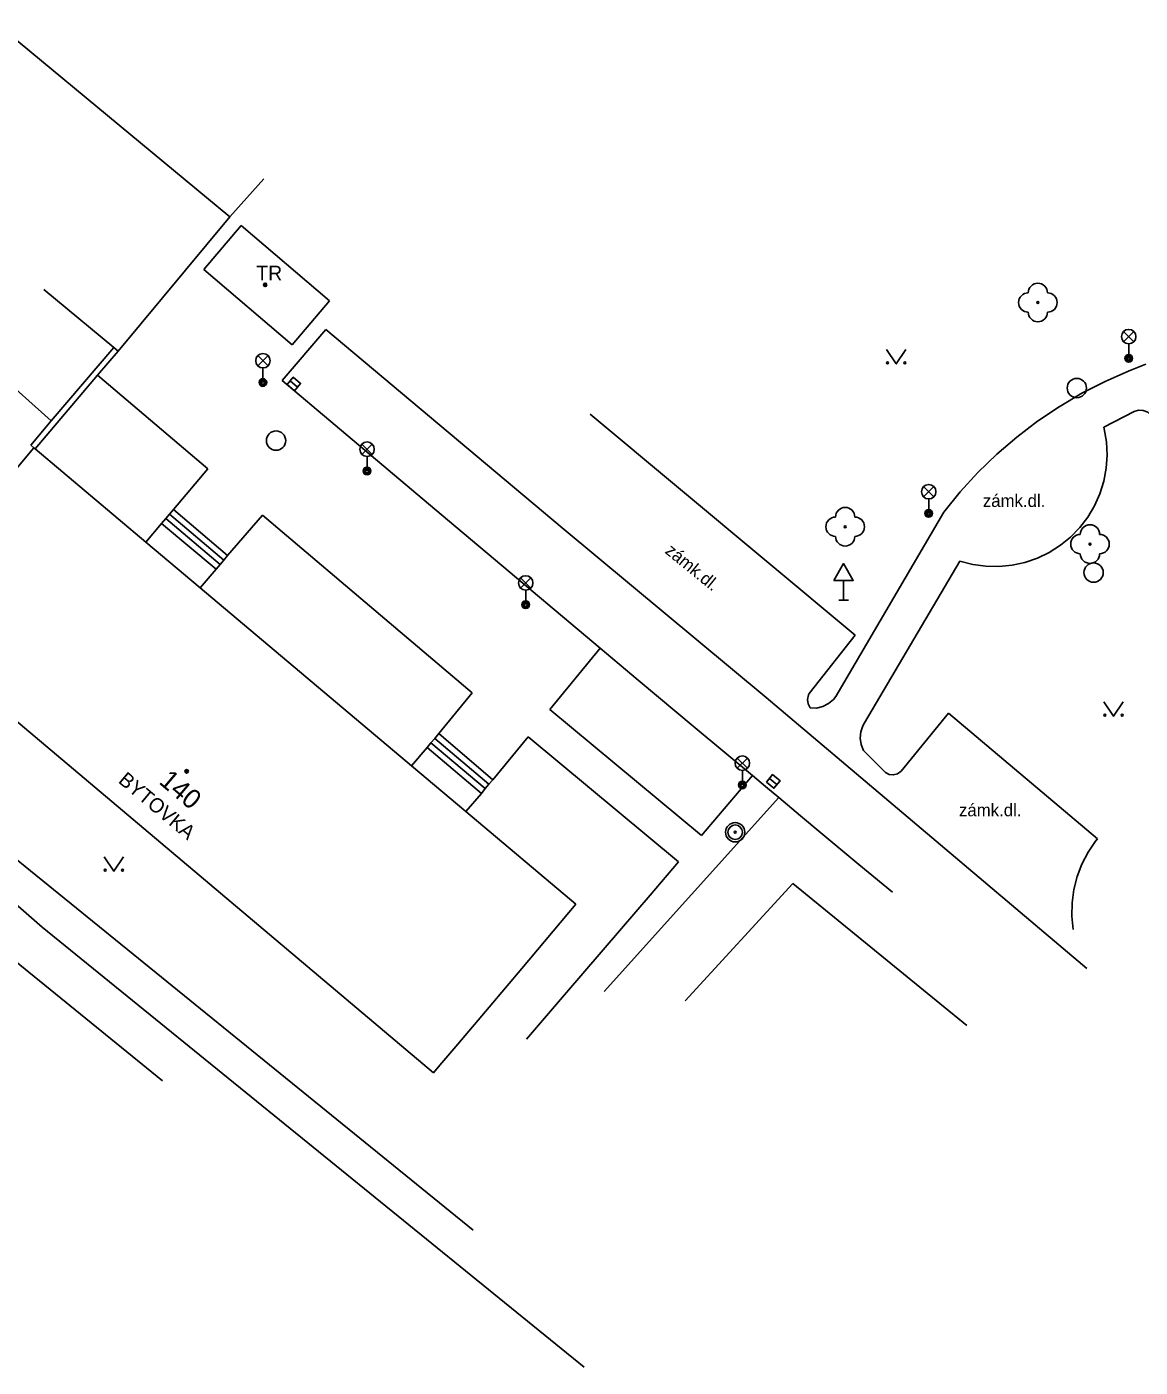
# Model space of a CAD drawing. Extents: x -538441 to -536770, y -1181008 to -1179809.
# Drawn here: x -537661.2 to -537603.6, y -1180951.6 to -1180882.2 of the extents above; entities that cross this region are included whole.
import ezdxf

# ---------------------------------------------------------------- set-up
doc = ezdxf.new("R2010")
doc.units = 0
for name, color, linetype in [('Vrstva 10', 7, 'Continuous'), ('Vrstva 11', 7, 'Continuous'), ('Vrstva 21', 7, 'Continuous'), ('Vrstva 22', 7, 'Continuous'), ('Vrstva 27', 7, 'Continuous'), ('Vrstva 33', 7, 'Continuous'), ('Vrstva 34', 7, 'Continuous'), ('Vrstva 36', 7, 'Continuous'), ('Vrstva 39', 7, 'Continuous'), ('Vrstva 40', 7, 'Continuous'), ('Vrstva 41', 7, 'Continuous'), ('Vrstva 47', 7, 'Continuous'), ('Vrstva 5', 7, 'Continuous'), ('Vrstva 7', 7, 'Continuous')]:
    doc.layers.add(name, color=color, linetype=linetype)

msp = doc.modelspace()

# ---------------------------------------------------------------- linework, layer by layer
at = {"layer": 'Vrstva 10'}
msp.add_line((-537654.22, -1180936.79), (-537662.16, -1180930.33), dxfattribs=at)
at = {"layer": 'Vrstva 11'}
for p, q in [((-537648.04, -1180900.54), (-537645.77, -1180897.89)), ((-537633.54, -1180908.16), (-537645.77, -1180897.89)), ((-537657.584, -1180900.269), (-537651.88, -1180905.11)), ((-537648.04, -1180900.54), (-537639.805, -1180907.47)), ((-537618.375, -1180913.717), (-537632.093, -1180902.282)), ((-537605.509, -1180902.952), (-537603.949, -1180902.141)), ((-537660.46, -1180928.83), (-537689.73, -1180903.18)), ((-537653.66, -1180907.21), (-537651.88, -1180905.11)), ((-537653.66, -1180907.21), (-537650.86, -1180909.6)), ((-537619.386, -1180916.895), (-537613.799, -1180907.355)), ((-537654.27, -1180907.934), (-537651.45, -1180910.31)), ((-537654.061, -1180907.686), (-537651.246, -1180910.058)), ((-537653.868, -1180907.457), (-537651.053, -1180909.829)), ((-537650.86, -1180909.6), (-537649.05, -1180907.5)), ((-537649.05, -1180907.5), (-537638.21, -1180916.7)), ((-537639.805, -1180907.47), (-537631.57, -1180914.4)), ((-537617.891, -1180918.257), (-537612.96, -1180909.882)), ((-537620.756, -1180916.741), (-537618.375, -1180913.717)), ((-537634.19, -1180917.57), (-537631.57, -1180914.4)), ((-537638.21, -1180916.7), (-537639.93, -1180918.81)), ((-537626.34, -1180924.09), (-537634.19, -1180917.57)), ((-537613.552, -1180917.763), (-537616.001, -1180920.764)), ((-537605.84, -1180924.255), (-537613.552, -1180917.763)), ((-537640.142, -1180919.062), (-537637.333, -1180921.429)), ((-537639.93, -1180918.81), (-537637.14, -1180921.2)), ((-537637.14, -1180921.2), (-537635.3, -1180918.98)), ((-537635.3, -1180918.98), (-537627.52, -1180925.46)), ((-537640.536, -1180919.529), (-537637.71, -1180921.91)), ((-537640.335, -1180919.291), (-537637.526, -1180921.658)), ((-537638.15, -1180944.52), (-537667.864, -1180920.389)), ((-537623.7, -1180920.99), (-537626.34, -1180924.09)), ((-537631.371, -1180932.162), (-537622.34, -1180922.13)), ((-537660.46, -1180928.83), (-537632.41, -1180951.61))]:
    msp.add_line(p, q, dxfattribs=at)
for points in [[(-537613.799, -1180907.355), (-537612.943, -1180906.303), (-537612.025, -1180905.303), (-537611.051, -1180904.358), (-537610.023, -1180903.473), (-537608.944, -1180902.65), (-537607.819, -1180901.892), (-537606.651, -1180901.201), (-537605.444, -1180900.581), (-537604.203, -1180900.033), (-537603.336, -1180899.7)], [(-537603.949, -1180902.141), (-537603.714, -1180902.073), (-537603.471, -1180902.085), (-537603.243, -1180902.174), (-537603.057, -1180902.331), (-537602.959, -1180902.477)], [(-537612.96, -1180909.882), (-537612.3, -1180910.054), (-537611.624, -1180910.148), (-537610.942, -1180910.162), (-537610.263, -1180910.097), (-537609.597, -1180909.952), (-537608.951, -1180909.73), (-537608.337, -1180909.435), (-537607.76, -1180909.069), (-537607.231, -1180908.639), (-537606.756, -1180908.15), (-537606.341, -1180907.608), (-537605.992, -1180907.022), (-537605.715, -1180906.399), (-537605.512, -1180905.747), (-537605.386, -1180905.077), (-537605.34, -1180904.396), (-537605.374, -1180903.715), (-537605.488, -1180903.042), (-537605.509, -1180902.952)], [(-537655.085, -1180908.901), (-537654.27, -1180907.934), (-537654.061, -1180907.686), (-537653.868, -1180907.457), (-537653.66, -1180907.21)], [(-537633.54, -1180908.16), (-537622.985, -1180916.939), (-537606.4, -1180930.966)], [(-537652.27, -1180911.273), (-537651.45, -1180910.31), (-537651.246, -1180910.058), (-537651.053, -1180909.829), (-537650.86, -1180909.6)], [(-537631.57, -1180914.4), (-537629.605, -1180916.05), (-537626.653, -1180918.52)], [(-537620.718, -1180917.488), (-537620.82, -1180917.275), (-537620.845, -1180917.041), (-537620.791, -1180916.811), (-537620.756, -1180916.741)], [(-537620.718, -1180917.488), (-537620.384, -1180917.491), (-537620.059, -1180917.415), (-537619.761, -1180917.264), (-537619.507, -1180917.047), (-537619.386, -1180916.895)], [(-537626.653, -1180918.52), (-537623.7, -1180920.99), (-537623.02, -1180921.56), (-537622.34, -1180922.13), (-537621.217, -1180923.069), (-537620.163, -1180923.947), (-537618.183, -1180925.589), (-537616.448, -1180927.022)], [(-537616.816, -1180920.821), (-537617.951, -1180919.694), (-537618.074, -1180919.384), (-537618.121, -1180919.053), (-537618.087, -1180918.72), (-537617.976, -1180918.405), (-537617.891, -1180918.257)], [(-537641.339, -1180920.482), (-537640.536, -1180919.529), (-537640.335, -1180919.291), (-537640.142, -1180919.062), (-537639.93, -1180918.81)], [(-537638.529, -1180922.849), (-537637.71, -1180921.91), (-537637.526, -1180921.658), (-537637.333, -1180921.429), (-537637.14, -1180921.2)], [(-537616.816, -1180920.821), (-537616.624, -1180920.925), (-537616.408, -1180920.953), (-537616.196, -1180920.902), (-537616.001, -1180920.764)], [(-537607.099, -1180928.962), (-537607.166, -1180928.271), (-537607.154, -1180927.577), (-537607.062, -1180926.889), (-537606.891, -1180926.217), (-537606.644, -1180925.568), (-537606.324, -1180924.952), (-537605.936, -1180924.377), (-537605.84, -1180924.255)], [(-537635.394, -1180934.63), (-537633.429, -1180932.335), (-537630.473, -1180928.898), (-537628.996, -1180927.18), (-537627.52, -1180925.46)]]:
    msp.add_lwpolyline(points, dxfattribs=at)
at = {"layer": 'Vrstva 21'}
for radius in [0.375, 0.05]:
    msp.add_circle((-537624.59, -1180923.92), radius, dxfattribs=at)
at = {"layer": 'Vrstva 22'}
for centre in [(-537608.927, -1180896.5), (-537618.898, -1180908.107), (-537606.229, -1180909.004)]:
    msp.add_circle(centre, 0.05, dxfattribs=at)
for centre, start, end in [((-537608.927, -1180896), 0, 180), ((-537609.427, -1180896.5), 90, 270), ((-537608.427, -1180896.5), 270, 90), ((-537608.927, -1180897), 180, 0), ((-537618.898, -1180907.607), 0, 180), ((-537619.398, -1180908.107), 90, 270), ((-537618.398, -1180908.107), 270, 90), ((-537606.229, -1180908.504), 0, 180), ((-537618.898, -1180908.607), 180, 0), ((-537606.729, -1180909.004), 90, 270), ((-537605.729, -1180909.004), 270, 90), ((-537606.229, -1180909.504), 180, 0)]:
    msp.add_arc(centre, 0.5, start, end, dxfattribs=at)
at = {"layer": 'Vrstva 27'}
for p, q in [((-537647.621, -1180900.559), (-537647.239, -1180900.881)), ((-537622.813, -1180921.131), (-537622.427, -1180921.449))]:
    msp.add_line(p, q, dxfattribs=at)
for points in [[(-537647.782, -1180900.75), (-537647.4, -1180901.072), (-537647.078, -1180900.69), (-537647.46, -1180900.368)], [(-537622.972, -1180921.323), (-537622.587, -1180921.642), (-537622.268, -1180921.257), (-537622.653, -1180920.938)]]:
    msp.add_lwpolyline(points, close=True, dxfattribs=at)
for centre in [(-537606.911, -1180900.927), (-537648.35, -1180903.65), (-537606.043, -1180910.48), (-537624.59, -1180923.92)]:
    msp.add_circle(centre, 0.5, dxfattribs=at)
at = {"layer": 'Vrstva 33'}
for p, q in [((-537604.489, -1180898.532), (-537603.959, -1180898.002)), ((-537604.489, -1180898.002), (-537603.959, -1180898.532)), ((-537604.224, -1180898.642), (-537604.224, -1180899.392)), ((-537649.295, -1180899.78), (-537648.765, -1180899.25)), ((-537649.295, -1180899.25), (-537648.765, -1180899.78)), ((-537649.03, -1180899.89), (-537649.03, -1180900.64)), ((-537643.907, -1180904.359), (-537643.377, -1180903.829)), ((-537643.907, -1180903.829), (-537643.377, -1180904.359)), ((-537643.642, -1180904.469), (-537643.642, -1180905.219)), ((-537614.841, -1180906.557), (-537614.311, -1180906.027)), ((-537614.841, -1180906.027), (-537614.311, -1180906.557)), ((-537614.576, -1180906.667), (-537614.576, -1180907.417)), ((-537635.695, -1180911.28), (-537635.165, -1180910.75)), ((-537635.695, -1180910.75), (-537635.165, -1180911.28)), ((-537635.43, -1180911.39), (-537635.43, -1180912.14)), ((-537624.485, -1180920.61), (-537623.955, -1180920.08)), ((-537624.485, -1180920.08), (-537623.955, -1180920.61)), ((-537624.22, -1180920.72), (-537624.22, -1180921.47))]:
    msp.add_line(p, q, dxfattribs=at)
for centre, radius in [((-537604.224, -1180898.267), 0.375), ((-537649.03, -1180899.515), 0.375), ((-537604.224, -1180899.392), 0.2), ((-537604.224, -1180899.392), 0.145), ((-537604.224, -1180899.392), 0.0876), ((-537649.03, -1180900.64), 0.2), ((-537649.03, -1180900.64), 0.145), ((-537649.03, -1180900.64), 0.0876), ((-537643.642, -1180904.094), 0.375), ((-537643.642, -1180905.219), 0.2), ((-537643.642, -1180905.219), 0.145), ((-537643.642, -1180905.219), 0.0876), ((-537614.576, -1180906.292), 0.375), ((-537614.576, -1180907.417), 0.2), ((-537614.576, -1180907.417), 0.145), ((-537614.576, -1180907.417), 0.0876), ((-537635.43, -1180911.015), 0.375), ((-537635.43, -1180912.14), 0.2), ((-537635.43, -1180912.14), 0.145), ((-537635.43, -1180912.14), 0.0876), ((-537624.22, -1180920.345), 0.375), ((-537624.22, -1180921.47), 0.2), ((-537624.22, -1180921.47), 0.145), ((-537624.22, -1180921.47), 0.0876)]:
    msp.add_circle(centre, radius, dxfattribs=at)
at = {"layer": 'Vrstva 34'}
for p, q in [((-537618.981, -1180910.882), (-537618.981, -1180911.9)), ((-537619.231, -1180911.9), (-537618.731, -1180911.9))]:
    msp.add_line(p, q, dxfattribs=at)
msp.add_lwpolyline([(-537619.481, -1180910.882), (-537618.481, -1180910.882), (-537618.981, -1180910.016)], close=True, dxfattribs=at)
at = {"layer": 'Vrstva 36'}
for points in [[(-537616.757, -1180898.926), (-537616.257, -1180899.676), (-537615.757, -1180898.926)], [(-537605.509, -1180917.162), (-537605.009, -1180917.912), (-537604.509, -1180917.162)], [(-537657.244, -1180925.185), (-537656.744, -1180925.935), (-537656.244, -1180925.185)]]:
    msp.add_lwpolyline(points, dxfattribs=at)
for centre in [(-537616.707, -1180899.626), (-537615.808, -1180899.626), (-537605.459, -1180917.862), (-537604.56, -1180917.862), (-537657.194, -1180925.885), (-537656.295, -1180925.885)]:
    msp.add_circle(centre, 0.05, dxfattribs=at)
at = {"layer": 'Vrstva 39'}
for centre, radius in [((-537648.918, -1180895.583), 0.09), ((-537648.918, -1180895.583), 0.0398), ((-537652.978, -1180920.764), 0.09), ((-537652.978, -1180920.764), 0.0398)]:
    msp.add_circle(centre, radius, dxfattribs=at)
at = {"layer": 'Vrstva 5'}
for p, q in [((-537667.36, -1180878.3), (-537650.74, -1180892.07)), ((-537656.52, -1180899.02), (-537650.74, -1180892.07)), ((-537652.088, -1180894.79), (-537650.163, -1180892.511)), ((-537650.163, -1180892.511), (-537645.59, -1180896.408)), ((-537652.088, -1180894.79), (-537647.515, -1180898.687)), ((-537659.987, -1180902.63), (-537668.11, -1180895.35)), ((-537647.515, -1180898.687), (-537645.59, -1180896.408)), ((-537660.881, -1180904.018), (-537668.2, -1180912.77)), ((-537668.2, -1180912.77), (-537640.2, -1180936.37)), ((-537621.609, -1180926.579), (-537627.179, -1180932.647))]:
    msp.add_line(p, q, dxfattribs=at)
for points in [[(-537660.364, -1180895.823), (-537656.75, -1180898.829), (-537656.52, -1180899.02)], [(-537632.83, -1180927.65), (-537638.529, -1180922.849), (-537641.339, -1180920.482), (-537652.27, -1180911.273), (-537655.085, -1180908.901), (-537660.82, -1180904.07)], [(-537612.611, -1180933.917), (-537614.197, -1180932.626), (-537621.609, -1180926.579)], [(-537632.83, -1180927.65), (-537635.634, -1180930.968), (-537637.33, -1180932.975), (-537638.951, -1180934.893), (-537639.873, -1180935.983), (-537640.2, -1180936.37)]]:
    msp.add_lwpolyline(points, dxfattribs=at)
at = {"layer": 'Vrstva 7'}
msp.add_line((-537648.98, -1180890.09), (-537650.74, -1180892.07), dxfattribs=at)
for points in [[(-537656.75, -1180898.829), (-537659.987, -1180902.63), (-537661.048, -1180903.876)], [(-537661.048, -1180903.876), (-537660.881, -1180904.018), (-537660.82, -1180904.07), (-537657.584, -1180900.269), (-537656.52, -1180899.02)]]:
    msp.add_lwpolyline(points, dxfattribs=at)

# ---------------------------------------------------------------- texts
at = {"layer": 'Vrstva 40'}
for p in [(-537611.775, -1180907.083), (-537613.01, -1180923.096)]:
    msp.add_text('zámk.dl.', height=0.65, dxfattribs=at).set_placement(p)
msp.add_text('zámk.dl.', height=0.65, rotation=320.83776, dxfattribs=at).set_placement((-537628.265, -1180909.436))
at = {"layer": 'Vrstva 41'}
msp.add_text('TR', height=0.75, dxfattribs=at).set_placement((-537649.371, -1180895.347))
msp.add_text('BYTOVKA', height=0.75, rotation=320.09247, dxfattribs=at).set_placement((-537656.562, -1180921.315))
at = {"layer": 'Vrstva 47'}
msp.add_text('140', height=1, rotation=319.8739, dxfattribs=at).set_placement((-537654.46, -1180921.367))

doc.saveas('drawing.dxf')
